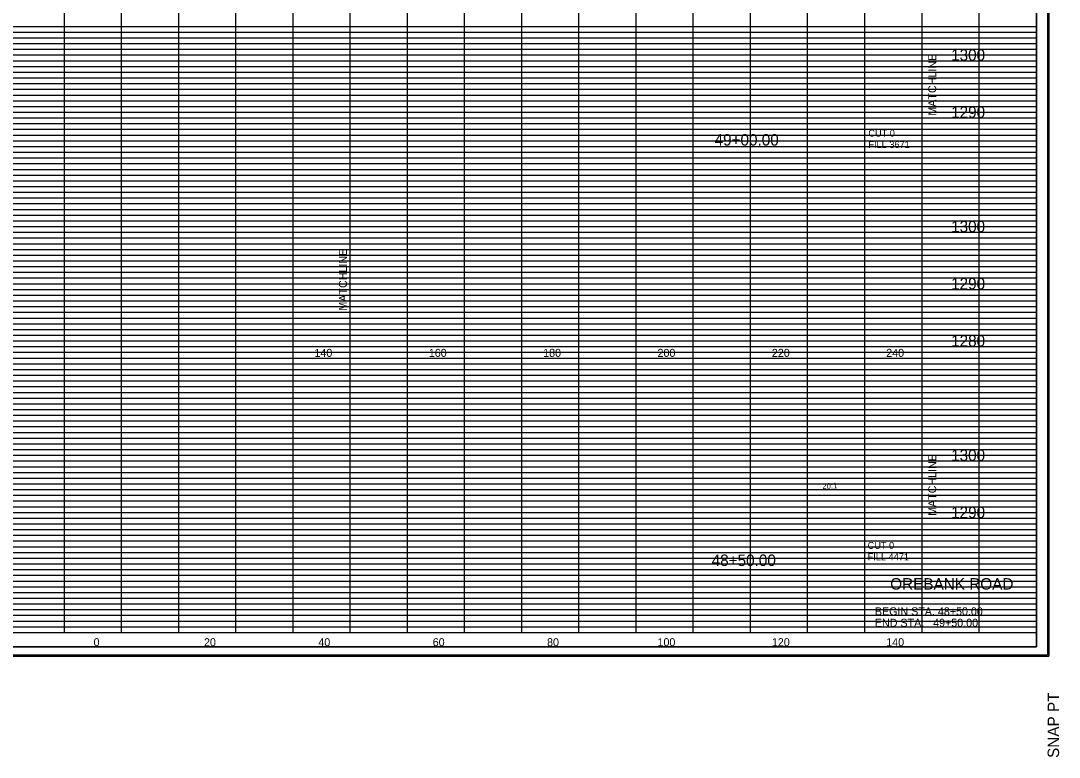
# Model space of a CAD drawing. Extents: x 980 to 1324, y 978 to 2847.
# Drawn here: x 1142.4 to 1324, y 2598.2 to 2727 of the extents above; entities that cross this region are included whole.
import ezdxf

# ---------------------------------------------------------------- set-up
doc = ezdxf.new("R2010")
doc.units = 0
for name, color, linetype in [('DESIGN - SHEET - Corner Text', 7, 'Continuous'), ('DESIGN - SHEET - Light Grid', 7, 'Continuous'), ('DESIGN - SHEET - Linework', 7, 'Continuous'), ('DESIGN - SHEET - Plot Shape', 7, 'Continuous'), ('DESIGN - TYPICAL - Finished Grade Slopes Text', 7, 'Continuous'), ('DESIGN - TYPICAL - Text', 7, 'Continuous')]:
    doc.layers.add(name, color=color, linetype=linetype)

# ---------------------------------------------------------------- blocks, each defined once
blk = doc.blocks.new('XSTSHT')
at = {"layer": 'DESIGN - SHEET - Light Grid'}
for p, q in [((8, 10.6), (16, 10.6)), ((16, 10.6), (24, 10.6)), ((24, 10.6), (32, 10.6)), ((8, 10.5), (16, 10.5)), ((8, 10.4), (16, 10.4)), ((16, 10.5), (24, 10.5)), ((16, 10.4), (24, 10.4)), ((24, 10.5), (32, 10.5)), ((24, 10.4), (32, 10.4)), ((8, 10.3), (16, 10.3)), ((8, 10.2), (16, 10.2)), ((16, 10.3), (24, 10.3)), ((16, 10.2), (24, 10.2)), ((24, 10.3), (32, 10.3)), ((24, 10.2), (32, 10.2)), ((8, 10.1), (16, 10.1)), ((16, 10.1), (24, 10.1)), ((24, 10.1), (32, 10.1)), ((8, 9.9), (16, 9.9)), ((16, 9.9), (24, 9.9)), ((24, 9.9), (32, 9.9)), ((8, 9.8), (16, 9.8)), ((8, 9.7), (16, 9.7)), ((16, 9.8), (24, 9.8)), ((16, 9.7), (24, 9.7)), ((24, 9.8), (32, 9.8)), ((24, 9.7), (32, 9.7)), ((8, 9.6), (16, 9.6)), ((8, 9.5), (16, 9.5)), ((16, 9.6), (24, 9.6)), ((16, 9.5), (24, 9.5)), ((24, 9.6), (32, 9.6)), ((24, 9.5), (32, 9.5)), ((8, 9.4), (16, 9.4)), ((8, 9.3), (16, 9.3)), ((16, 9.4), (24, 9.4)), ((16, 9.3), (24, 9.3)), ((24, 9.4), (32, 9.4)), ((24, 9.3), (32, 9.3)), ((8, 9.2), (16, 9.2)), ((8, 9.1), (16, 9.1)), ((16, 9.2), (24, 9.2)), ((16, 9.1), (24, 9.1)), ((24, 9.2), (32, 9.2)), ((24, 9.1), (32, 9.1)), ((8, 8.9), (16, 8.9)), ((16, 8.9), (24, 8.9)), ((24, 8.9), (32, 8.9)), ((8, 8.8), (16, 8.8)), ((16, 8.8), (24, 8.8)), ((24, 8.8), (32, 8.8)), ((8, 8.7), (16, 8.7)), ((8, 8.6), (16, 8.6)), ((16, 8.7), (24, 8.7)), ((16, 8.6), (24, 8.6)), ((24, 8.7), (32, 8.7)), ((24, 8.6), (32, 8.6)), ((8, 8.5), (16, 8.5)), ((8, 8.4), (16, 8.4)), ((16, 8.5), (24, 8.5)), ((16, 8.4), (24, 8.4)), ((24, 8.5), (32, 8.5)), ((24, 8.4), (32, 8.4)), ((8, 8.3), (16, 8.3)), ((8, 8.2), (16, 8.2)), ((16, 8.3), (24, 8.3)), ((16, 8.2), (24, 8.2)), ((24, 8.3), (32, 8.3)), ((24, 8.2), (32, 8.2)), ((8, 8.1), (16, 8.1)), ((16, 8.1), (24, 8.1)), ((24, 8.1), (32, 8.1)), ((8, 7.9), (16, 7.9)), ((16, 7.9), (24, 7.9)), ((24, 7.9), (32, 7.9)), ((8, 7.8), (16, 7.8)), ((8, 7.7), (16, 7.7)), ((16, 7.8), (24, 7.8)), ((16, 7.7), (24, 7.7)), ((24, 7.8), (32, 7.8)), ((24, 7.7), (32, 7.7)), ((8, 7.6), (16, 7.6)), ((8, 7.5), (16, 7.5)), ((16, 7.6), (24, 7.6)), ((16, 7.5), (24, 7.5)), ((24, 7.6), (32, 7.6)), ((24, 7.5), (32, 7.5)), ((8, 7.4), (16, 7.4)), ((8, 7.3), (16, 7.3)), ((16, 7.4), (24, 7.4)), ((16, 7.3), (24, 7.3)), ((24, 7.4), (32, 7.4)), ((24, 7.3), (32, 7.3)), ((8, 7.2), (16, 7.2)), ((8, 7.1), (16, 7.1)), ((16, 7.2), (24, 7.2)), ((16, 7.1), (24, 7.1)), ((24, 7.2), (32, 7.2)), ((24, 7.1), (32, 7.1)), ((8, 6.9), (16, 6.9)), ((8, 6.8), (16, 6.8)), ((16, 6.9), (24, 6.9)), ((16, 6.8), (24, 6.8)), ((24, 6.9), (32, 6.9)), ((24, 6.8), (32, 6.8)), ((8, 6.7), (16, 6.7)), ((8, 6.6), (16, 6.6)), ((16, 6.7), (24, 6.7)), ((16, 6.6), (24, 6.6)), ((24, 6.7), (32, 6.7)), ((24, 6.6), (32, 6.6)), ((8, 6.5), (16, 6.5)), ((8, 6.4), (16, 6.4)), ((16, 6.5), (24, 6.5)), ((16, 6.4), (24, 6.4)), ((24, 6.5), (32, 6.5)), ((24, 6.4), (32, 6.4)), ((8, 6.3), (16, 6.3)), ((8, 6.2), (16, 6.2)), ((16, 6.3), (24, 6.3)), ((16, 6.2), (24, 6.2)), ((24, 6.3), (32, 6.3)), ((24, 6.2), (32, 6.2)), ((8, 6.1), (16, 6.1)), ((16, 6.1), (24, 6.1)), ((24, 6.1), (32, 6.1)), ((8, 5.9), (16, 5.9)), ((16, 5.9), (24, 5.9)), ((24, 5.9), (32, 5.9)), ((8, 5.8), (16, 5.8)), ((8, 5.7), (16, 5.7)), ((16, 5.8), (24, 5.8)), ((16, 5.7), (24, 5.7)), ((24, 5.8), (32, 5.8)), ((24, 5.7), (32, 5.7)), ((8, 5.6), (16, 5.6)), ((8, 5.5), (16, 5.5)), ((16, 5.6), (24, 5.6)), ((16, 5.5), (24, 5.5)), ((24, 5.6), (32, 5.6)), ((24, 5.5), (32, 5.5)), ((8, 5.4), (16, 5.4)), ((8, 5.3), (16, 5.3)), ((16, 5.4), (24, 5.4)), ((16, 5.3), (24, 5.3)), ((24, 5.4), (32, 5.4)), ((24, 5.3), (32, 5.3)), ((8, 5.2), (16, 5.2)), ((8, 5.1), (16, 5.1)), ((16, 5.2), (24, 5.2)), ((16, 5.1), (24, 5.1)), ((24, 5.2), (32, 5.2)), ((24, 5.1), (32, 5.1)), ((8, 4.9), (16, 4.9)), ((8, 4.8), (16, 4.8)), ((16, 4.9), (24, 4.9)), ((16, 4.8), (24, 4.8)), ((24, 4.9), (32, 4.9)), ((24, 4.8), (32, 4.8)), ((8, 4.7), (16, 4.7)), ((8, 4.6), (16, 4.6)), ((16, 4.7), (24, 4.7)), ((16, 4.6), (24, 4.6)), ((24, 4.7), (32, 4.7)), ((24, 4.6), (32, 4.6)), ((8, 4.5), (16, 4.5)), ((8, 4.4), (16, 4.4)), ((16, 4.5), (24, 4.5)), ((16, 4.4), (24, 4.4)), ((24, 4.5), (32, 4.5)), ((24, 4.4), (32, 4.4)), ((8, 4.3), (16, 4.3)), ((8, 4.2), (16, 4.2)), ((16, 4.3), (24, 4.3)), ((16, 4.2), (24, 4.2)), ((24, 4.3), (32, 4.3)), ((24, 4.2), (32, 4.2)), ((8, 4.1), (16, 4.1)), ((16, 4.1), (24, 4.1)), ((24, 4.1), (32, 4.1)), ((8, 3.9), (16, 3.9)), ((16, 3.9), (24, 3.9)), ((24, 3.9), (32, 3.9)), ((8, 3.8), (16, 3.8)), ((8, 3.7), (16, 3.7)), ((16, 3.8), (24, 3.8)), ((16, 3.7), (24, 3.7)), ((24, 3.8), (32, 3.8)), ((24, 3.7), (32, 3.7)), ((8, 3.6), (16, 3.6)), ((8, 3.5), (16, 3.5)), ((16, 3.6), (24, 3.6)), ((16, 3.5), (24, 3.5)), ((24, 3.6), (32, 3.6)), ((24, 3.5), (32, 3.5)), ((8, 3.4), (16, 3.4)), ((8, 3.3), (16, 3.3)), ((16, 3.4), (24, 3.4)), ((16, 3.3), (24, 3.3)), ((24, 3.4), (32, 3.4)), ((24, 3.3), (32, 3.3)), ((8, 3.2), (16, 3.2)), ((8, 3.1), (16, 3.1)), ((16, 3.2), (24, 3.2)), ((16, 3.1), (24, 3.1)), ((24, 3.2), (32, 3.2)), ((24, 3.1), (32, 3.1)), ((8, 2.9), (16, 2.9)), ((8, 2.8), (16, 2.8)), ((16, 2.9), (24, 2.9)), ((16, 2.8), (24, 2.8)), ((24, 2.9), (32, 2.9)), ((24, 2.8), (32, 2.8)), ((8, 2.7), (16, 2.7)), ((8, 2.6), (16, 2.6)), ((16, 2.7), (24, 2.7)), ((16, 2.6), (24, 2.6)), ((24, 2.7), (32, 2.7)), ((24, 2.6), (32, 2.6)), ((8, 2.5), (16, 2.5)), ((8, 2.4), (16, 2.4)), ((16, 2.5), (24, 2.5)), ((16, 2.4), (24, 2.4)), ((24, 2.5), (32, 2.5)), ((24, 2.4), (32, 2.4)), ((8, 2.3), (16, 2.3)), ((8, 2.2), (16, 2.2)), ((16, 2.3), (24, 2.3)), ((16, 2.2), (24, 2.2)), ((24, 2.3), (32, 2.3)), ((24, 2.2), (32, 2.2)), ((8, 2.1), (16, 2.1)), ((16, 2.1), (24, 2.1)), ((24, 2.1), (32, 2.1)), ((8, 1.9), (16, 1.9)), ((16, 1.9), (24, 1.9)), ((24, 1.9), (32, 1.9)), ((8, 1.8), (16, 1.8)), ((8, 1.7), (16, 1.7)), ((16, 1.8), (24, 1.8)), ((16, 1.7), (24, 1.7)), ((24, 1.8), (32, 1.8)), ((24, 1.7), (32, 1.7)), ((8, 1.6), (16, 1.6)), ((8, 1.5), (16, 1.5)), ((16, 1.6), (24, 1.6)), ((16, 1.5), (24, 1.5)), ((24, 1.6), (32, 1.6)), ((24, 1.5), (32, 1.5)), ((8, 1.4), (16, 1.4)), ((8, 1.3), (16, 1.3)), ((16, 1.4), (24, 1.4)), ((16, 1.3), (24, 1.3)), ((24, 1.4), (32, 1.4)), ((24, 1.3), (32, 1.3)), ((8, 1.2), (16, 1.2)), ((8, 1.1), (16, 1.1)), ((16, 1.2), (24, 1.2)), ((16, 1.1), (24, 1.1)), ((24, 1.2), (32, 1.2)), ((24, 1.1), (32, 1.1)), ((8, 0.9), (16, 0.9)), ((8, 0.8), (16, 0.8)), ((16, 0.9), (24, 0.9)), ((16, 0.8), (24, 0.8)), ((24, 0.9), (32, 0.9)), ((24, 0.8), (32, 0.8)), ((8, 0.7), (16, 0.7)), ((8, 0.6), (16, 0.6)), ((16, 0.7), (24, 0.7)), ((16, 0.6), (24, 0.6)), ((24, 0.7), (32, 0.7)), ((24, 0.6), (32, 0.6)), ((8, 0.5), (16, 0.5)), ((8, 0.4), (16, 0.4)), ((16, 0.5), (24, 0.5)), ((16, 0.4), (24, 0.4)), ((24, 0.5), (32, 0.5)), ((24, 0.4), (32, 0.4)), ((8, 0.3), (16, 0.3)), ((8, 0.2), (16, 0.2)), ((16, 0.3), (24, 0.3)), ((16, 0.2), (24, 0.2)), ((24, 0.3), (32, 0.3)), ((24, 0.2), (32, 0.2)), ((8, 0.1), (16, 0.1)), ((16, 0.1), (24, 0.1)), ((24, 0.1), (32, 0.1))]:
    blk.add_line(p, q, dxfattribs=at)
at = {"layer": 'DESIGN - SHEET - Linework'}
for p, q in [((32.217, 21.414), (32.217, -0.414)), ((15, 0), (15, 21)), ((16, 0), (16, 21)), ((17, 0), (17, 21)), ((18, 0), (18, 21)), ((19, 0), (19, 21)), ((20, 0), (20, 21)), ((21, 0), (21, 21)), ((22, 0), (22, 21)), ((23, 0), (23, 21)), ((24, 0), (24, 21)), ((25, 0), (25, 21)), ((26, 0), (26, 21)), ((27, 0), (27, 21)), ((28, 0), (28, 20)), ((29, 0), (29, 20)), ((30, 0), (30, 20)), ((31, 0), (31, 20)), ((0, 10), (32, 10)), ((0, 9), (32, 9)), ((0, 8), (32, 8)), ((0, 7), (32, 7)), ((0, 6), (32, 6)), ((0, 5), (32, 5)), ((0, 4), (32, 4)), ((0, 3), (32, 3)), ((0, 2), (32, 2)), ((0, 1), (32, 1)), ((-1.823, -0.414), (32.217, -0.414))]:
    blk.add_line(p, q, dxfattribs=at)
blk.add_lwpolyline([(0, 21), (0, 0), (32, 0), (32, 21), (0, 21)], dxfattribs=at)
at = {"layer": 'DESIGN - SHEET - Plot Shape'}
for points in [[(-1.803, 21.394), (32.197, 21.394), (32.197, -0.394), (-1.803, -0.394)], [(-0.85, 21), (32, 21), (32, -0.25), (-0.85, -0.25)]]:
    blk.add_lwpolyline(points, close=True, dxfattribs=at)
at = {"layer": 'DESIGN - SHEET - Corner Text'}
blk.add_text('SNAP PT  ', height=0.2, rotation=90, dxfattribs=at).set_placement((32.397, -2.194))

msp = doc.modelspace()

# ---------------------------------------------------------------- linework, layer by layer
at = {"layer": 'DESIGN - SHEET - Plot Shape'}
msp.add_lwpolyline([(991.5, 2617.5), (1320, 2617.5), (1320, 2830), (991.5, 2830)], close=True, dxfattribs=at)
at = {"layer": 'DESIGN - TYPICAL - Text'}
for p, q in [((1300, 2704.02), (1300, 2726.97)), ((1200, 2670), (1200, 2695.85)), ((1300, 2634.02), (1300, 2656.97))]:
    msp.add_line(p, q, dxfattribs=at)

# ---------------------------------------------------------------- block references
at = {"layer": 'DESIGN - SHEET - Plot Shape', "xscale": 10, "yscale": 10}
msp.add_blockref('XSTSHT', (1000, 2620), dxfattribs=at)

# ---------------------------------------------------------------- texts
at = {"layer": 'DESIGN - SHEET - Corner Text'}
for s, height, p in [('OREBANK ROAD', 2, (1294.44, 2627.5)), ('BEGIN STA. 48+50.00', 1.4, (1291.75, 2623)), ('END STA.   49+50.00', 1.4, (1291.75, 2621))]:
    msp.add_text(s, height=height, dxfattribs=at).set_placement(p)
at = {"layer": 'DESIGN - TYPICAL - Finished Grade Slopes Text'}
msp.add_text('20:1', height=1, rotation=2.8624, dxfattribs=at).set_placement((1282.59, 2645.08))
at = {"layer": 'DESIGN - TYPICAL - Text'}
for p in [(1302.49, 2710.39), (1199.42, 2676.29), (1302.49, 2640.39)]:
    msp.add_text('MATCHLINE', height=1.4, rotation=90, dxfattribs=at).set_placement(p)
for s, height, p in [('     1300     ', 2, (1301.37, 2720)), ('     1290     ', 2, (1301.37, 2710)), ('     49+00.00     ', 2, (1260, 2705.16)), ('CUT 0', 1.2, (1290.62, 2706.73)), ('FILL 3671', 1.2, (1290.62, 2704.73)), ('     1300     ', 2, (1301.37, 2690)), ('     1290     ', 2, (1301.37, 2680)), ('     1280     ', 2, (1301.37, 2670)), ('     140     ', 1.4, (1191.14, 2668.2)), ('     160     ', 1.4, (1211.14, 2668.2)), ('     180     ', 1.4, (1231.14, 2668.2)), ('     200     ', 1.4, (1251.14, 2668.2)), ('     220     ', 1.4, (1271.14, 2668.2)), ('     240     ', 1.4, (1291.14, 2668.2)), ('     1300     ', 2, (1301.37, 2650)), ('     1290     ', 2, (1301.37, 2640)), ('CUT 0', 1.2, (1290.49, 2634.63)), ('     48+50.00     ', 2, (1259.49, 2631.63)), ('FILL 4471', 1.2, (1290.49, 2632.63)), ('     0     ', 1.4, (1152.51, 2617.6)), ('     0     ', 1.4, (1152.51, 2617.6)), ('     20     ', 1.4, (1171.82, 2617.6)), ('     40     ', 1.4, (1191.82, 2617.6)), ('     60     ', 1.4, (1211.82, 2617.6)), ('     80     ', 1.4, (1231.82, 2617.6)), ('     100     ', 1.4, (1251.14, 2617.6)), ('     120     ', 1.4, (1271.14, 2617.6)), ('     140     ', 1.4, (1291.14, 2617.6))]:
    msp.add_text(s, height=height, dxfattribs=at).set_placement(p)

doc.saveas('drawing.dxf')
